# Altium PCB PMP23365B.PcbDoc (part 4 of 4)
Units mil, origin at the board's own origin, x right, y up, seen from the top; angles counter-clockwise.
Board outline 5450 x 2600 mil, 4 copper layers (Top Layer, Signal Layer 1, Signal Layer 2, Bottom Layer), stack 61.2 mil thick; 303 components, 149 nets, 783 pads, 285 vias.
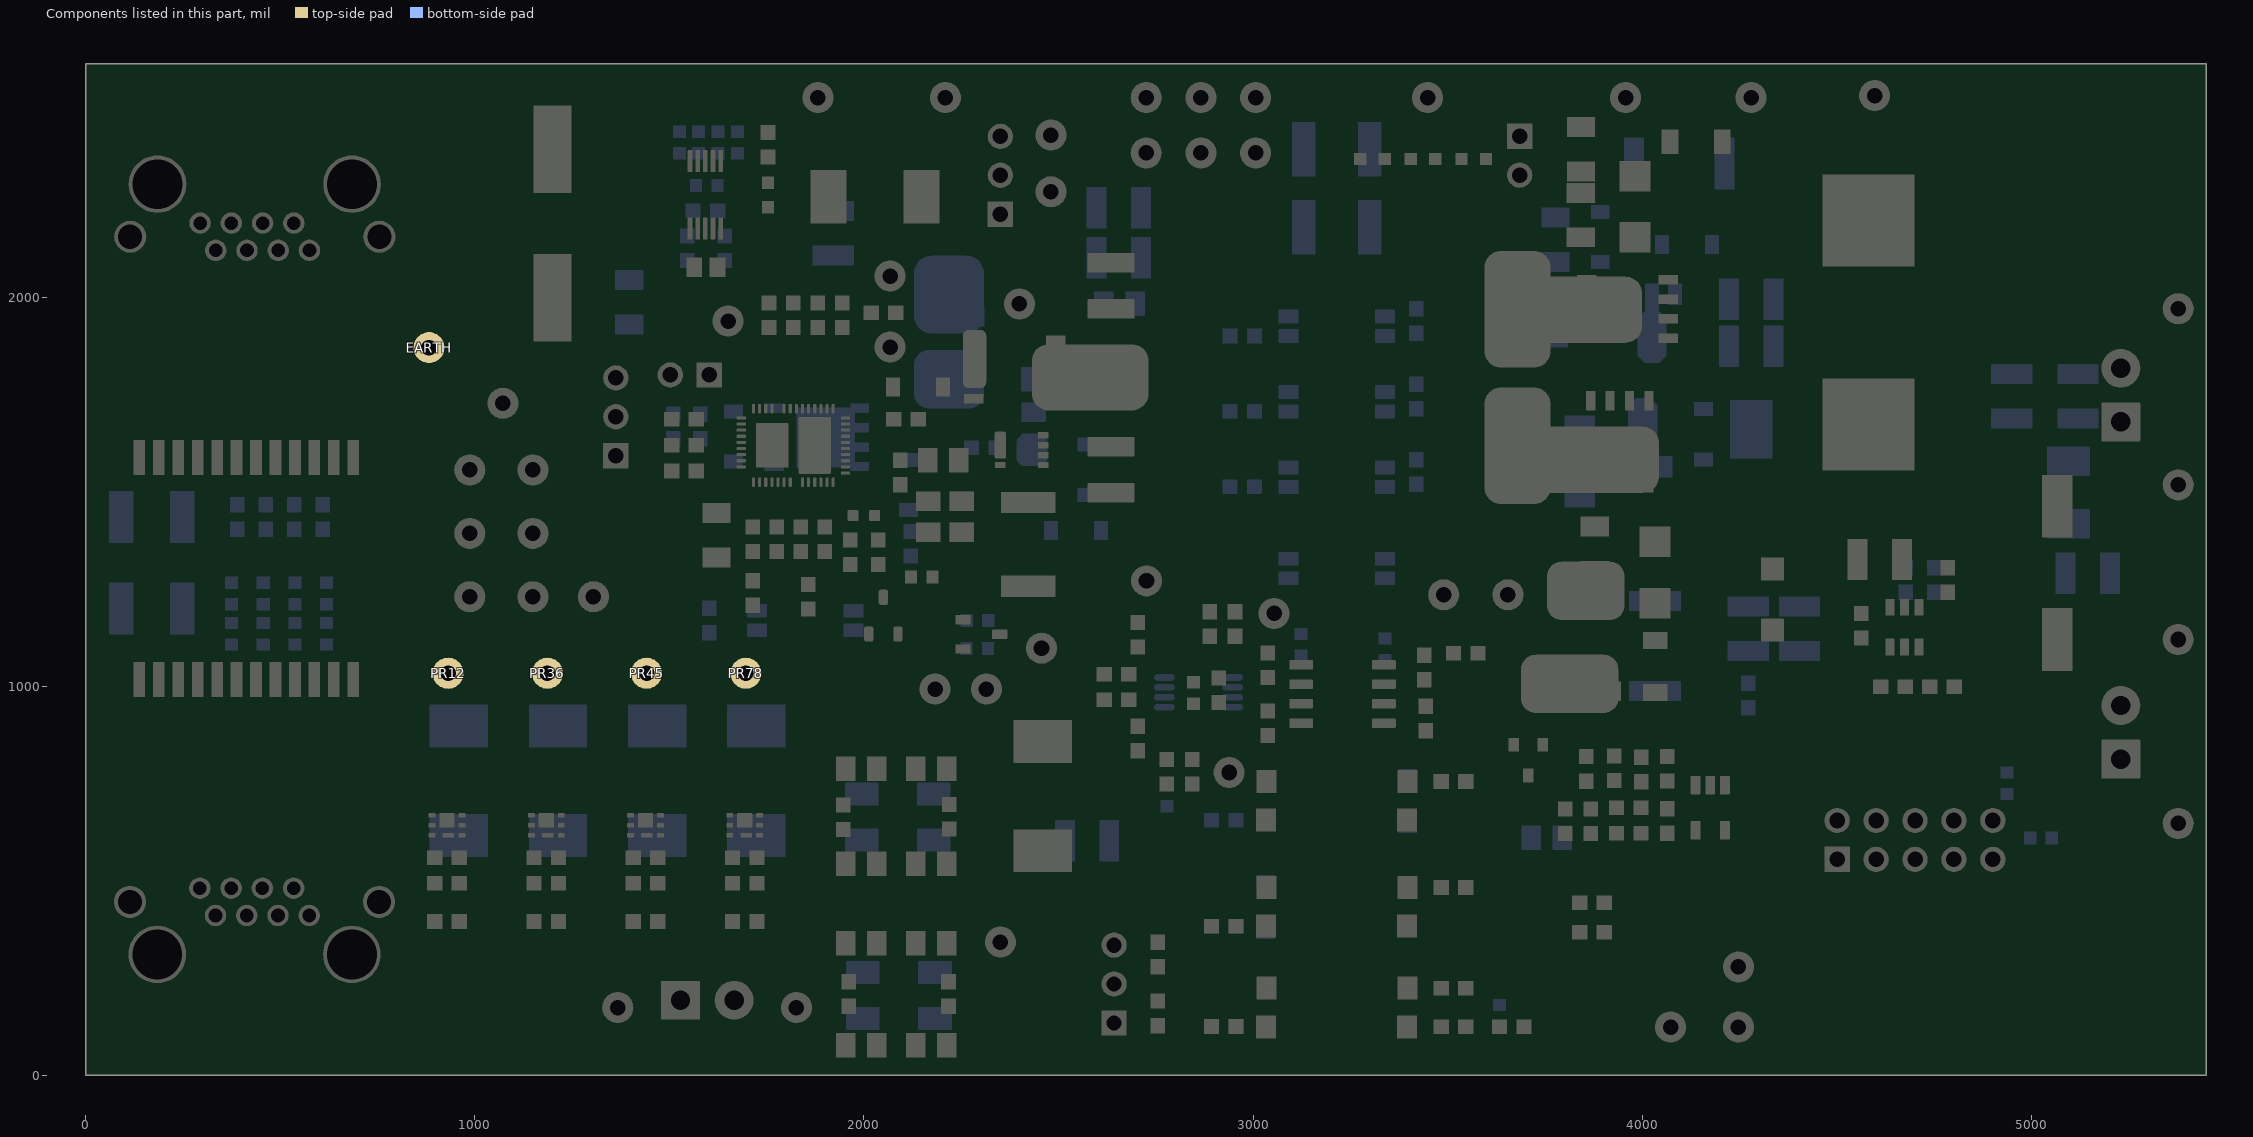
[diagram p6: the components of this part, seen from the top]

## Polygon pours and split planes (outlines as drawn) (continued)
NetC19_2 on Top Layer "TOP_LAYER_NETC19_2_P014" (solid, pour order 14): 3785.14,1540.97 cw(c3632.79,1409.24) 3833.66,1394.63 cw(c3823.69,1384.64) 3837.81,1384.62 3839.54,1382.89 ccw(c3842.66,1386.01) 3842.66,1381.6 3916.67,1381.6 cw(c3916.68,1314.41) 3964.2,1361.91 3987.72,1338.39 cw(c3984.07,1334.73) 3989.24,1334.72 ccw(c3997.54,1334.72) 3991.67,1328.85 3992.07,1328.45 ccw(c3998.48,1334.86) 3998.48,1325.79 4064.36,1325.79 ccw(c4064.36,1351.84) 4082.78,1333.42 ccw(c4071.04,1345.16) 4087.64,1345.17 4087.64,1499.56 cw(c4187.64,1499.56) 4116.93,1570.27 3901.74,1615.21
NetC19_2 on Top Layer "TOP_LAYER_NETC19_2_P011" (solid, pour order 11): 3733.67,1766.1 cw(c3733.67,1748.95) 3745.79,1761.08 3801.53,1705.33 ccw(c3872.24,1776.04) 3872.24,1676.04 4042.01,1676.04 cw(c4042.01,1663.92) 4050.58,1672.49 cw(c4036.08,1658) 4056.58,1658 4056.58,1550.67 cw(c3980.82,1550.67) 4034.39,1497.1 cw(c4020.56,1510.93) 4020.56,1491.37 3811.38,1491.37 ccw(c3811.38,1413.48) 3756.3,1468.56 cw(c3742.47,1482.39) 3742.47,1462.83 3630,1462.83 cw(c3630,1475.14) 3621.3,1466.44 3601.38,1486.35 cw(c3627.25,1512.22) 3590.67,1512.22 3590.67,1732.22 cw(c3617.55,1732.22) 3598.54,1751.23 cw(c3634.43,1715.35) 3634.43,1766.1
NetC31_1 on Top Layer "TOP_LAYER_NETC31_1_P009" (solid, pour order 9): 2339.58,1914.13 cw(c2345.74,1907.98) 2345.74,1916.68 2492.54,1916.68 cw(c2492.54,1878.68) 2519.41,1905.55 2531.01,1893.95 ccw(c2562.44,1925.38) 2562.44,1880.93 2689.57,1880.93 cw(c2689.57,1838.05) 2719.89,1868.37 cw(c2691.75,1840.23) 2731.54,1840.23 2731.54,1752.08 cw(c2678.31,1752.08) 2715.95,1714.44 cw(c2697.86,1732.53) 2697.86,1706.94 2350.16,1706.94 cw(c2350.16,1716.25) 2343.57,1709.67 2339.9,1713.34
NetC18_2 on Top Layer "TOP_LAYER_NETC18_2_P008" (solid, pour order 8): 2369.21,2113.07 2532.32,2113.07 ccw(c2532.32,2155.28) 2562.17,2125.43 cw(c2585.26,2102.34) 2585.26,2135 2666.53,2135 cw(c2666.53,2084.94) 2701.93,2120.34 2708.65,2113.63 cw(c2645.02,2050) 2735,2050 2735,1969.68 cw(c2721.29,1969.68) 2730.98,1959.99 2715.76,1944.77 cw(c2700.23,1960.3) 2700.23,1938.33 2597.39,1938.33 cw(c2597.39,1988.15) 2562.17,1952.92 2479.97,2035.12 ccw(c2409.26,1964.41) 2409.26,2064.41 2390.08,2064.41 2390.08,2075.64 ccw(c2364.2,2075.64) 2382.5,2093.94
NetC10_2 on Top Layer "TOP_LAYER_NETC10_2_P007" (solid, pour order 7): 1741.89,623.79 cw(c1741.89,616.2) 1747.25,621.57 1750.59,618.23 cw(c1739.95,607.59) 1755,607.59 1755,477.41 cw(c1750.3,477.41) 1753.62,474.09 1746.31,466.77 1719.49,466.77 cw(c1719.49,480.4) 1709.85,470.76 1704.29,476.33 1704.29,476.61 1703.31,477.59 cw(c1709.14,483.42) 1700.9,483.42 1700.9,578.34 ccw(c1684.33,578.34) 1696.04,590.06 1682.17,603.93 cw(c1687.01,608.77) 1680.16,608.77 1680.16,619.56 cw(c1684.16,619.56) 1681.33,622.38 cw(c1684.75,618.96) 1684.75,623.8 1741.6,623.8
NetC10_2 on Top Layer "TOP_LAYER_NETC10_2_P006" (solid, pour order 6): 1486.89,623.79 cw(c1486.89,616.2) 1492.25,621.57 1495.59,618.23 cw(c1484.95,607.59) 1500,607.59 1500,477.41 cw(c1495.3,477.41) 1498.62,474.09 1491.31,466.77 1464.49,466.77 cw(c1464.49,480.4) 1454.85,470.76 1449.29,476.33 1449.29,476.61 1448.31,477.59 cw(c1454.14,483.42) 1445.9,483.42 1445.9,578.34 ccw(c1429.33,578.34) 1441.04,590.06 1427.17,603.93 cw(c1432.01,608.77) 1425.16,608.77 1425.16,619.56 cw(c1429.16,619.56) 1426.33,622.38 cw(c1429.75,618.96) 1429.75,623.8 1486.6,623.8
NetC10_2 on Top Layer "TOP_LAYER_NETC10_2_P005" (solid, pour order 5): 1228.93,623.79 cw(c1228.93,616.2) 1234.3,621.57 1237.64,618.23 cw(c1227,607.59) 1242.05,607.59 1242.05,477.41 cw(c1237.35,477.41) 1240.67,474.09 1233.35,466.77 1206.54,466.77 cw(c1206.54,480.4) 1196.9,470.76 1191.34,476.33 1191.34,476.61 1190.36,477.59 cw(c1196.19,483.42) 1187.94,483.42 1187.94,578.34 ccw(c1171.38,578.34) 1183.09,590.06 1169.22,603.93 cw(c1174.06,608.77) 1167.21,608.77 1167.21,619.56 cw(c1171.2,619.56) 1168.38,622.38 cw(c1171.8,618.96) 1171.8,623.8 1228.65,623.8
NetC10_2 on Top Layer "TOP_LAYER_NETC10_2_P004" (solid, pour order 4): 976.89,623.79 cw(c976.89,616.2) 982.25,621.57 985.59,618.23 cw(c974.95,607.59) 990,607.59 990,477.41 cw(c985.3,477.41) 988.62,474.09 981.31,466.77 954.49,466.77 cw(c954.49,480.4) 944.86,470.76 939.29,476.33 939.29,476.61 938.31,477.59 cw(c944.14,483.42) 935.9,483.42 935.9,578.34 ccw(c919.33,578.34) 931.05,590.06 917.17,603.93 cw(c922.01,608.77) 915.16,608.77 915.16,619.56 cw(c919.16,619.56) 916.33,622.38 cw(c919.75,618.96) 919.75,623.8 976.6,623.8
PR78 on Top Layer "TOP_LAYER_PR78_P003" (solid, pour order 3): 1635.44,642.58 1635.44,747.48 cw(c1677.13,747.48) 1647.65,776.96 cw(c1679.22,745.39) 1679.22,790.03 1725.92,790.03 cw(c1725.92,745.39) 1757.49,776.96 cw(c1732.95,752.42) 1767.65,752.42 1767.65,668.5 cw(c1734.15,668.5) 1757.84,644.8 1752.07,639.04 cw(c1739.27,651.84) 1739.27,633.73 1645.53,633.73 cw(c1645.53,638.17) 1642.4,635.03 1635.86,641.57 cw(c1636.86,642.58) 1635.44,642.58
PR45 on Top Layer "TOP_LAYER_PR45_P002" (solid, pour order 2): 1379.56,642.58 1379.56,747.48 cw(c1421.25,747.48) 1391.77,776.96 cw(c1423.34,745.39) 1423.34,790.03 1470.04,790.03 cw(c1470.04,745.39) 1501.61,776.96 cw(c1477.07,752.42) 1511.77,752.42 1511.77,668.5 cw(c1478.26,668.5) 1501.96,644.8 1496.19,639.04 cw(c1483.38,651.84) 1483.38,633.73 1389.65,633.73 cw(c1389.65,638.17) 1386.52,635.03 1379.97,641.57 cw(c1380.97,642.58) 1379.56,642.58
PR36 on Top Layer "TOP_LAYER_PR36_P001" (solid, pour order 1): 1123.67,642.58 1123.67,747.48 cw(c1165.36,747.48) 1135.88,776.96 cw(c1167.45,745.39) 1167.45,790.03 1214.15,790.03 cw(c1214.15,745.39) 1245.72,776.96 cw(c1221.18,752.42) 1255.88,752.42 1255.88,668.5 cw(c1222.38,668.5) 1246.07,644.8 1240.3,639.04 cw(c1227.5,651.84) 1227.5,633.73 1133.77,633.73 cw(c1133.77,638.17) 1130.63,635.03 1124.09,641.57 cw(c1125.09,642.58) 1123.67,642.58
PR12 on Top Layer "TOP_LAYER_PR12_P000" (solid, pour order 0): 867.79,642.58 867.79,747.48 cw(c909.48,747.48) 880,776.96 cw(c911.57,745.39) 911.57,790.03 958.27,790.03 cw(c958.27,745.39) 989.84,776.96 cw(c965.3,752.42) 1000,752.42 1000,668.5 cw(c966.5,668.5) 990.19,644.8 984.42,639.04 cw(c971.61,651.84) 971.61,633.73 877.88,633.73 cw(c877.88,638.17) 874.75,635.03 868.2,641.57 cw(c869.21,642.58) 867.79,642.58
PGND on Bottom Layer "BOTTOM_LAYER_PGND_P038" (solid, pour order 38): 1230.78,2575 ccw(c1230.78,2506.72) 1182.5,2555 1132.41,2504.91 ccw(c1159.33,2477.99) 1121.26,2477.99 1121.26,1962.21 ccw(c1217.21,1962.21) 1149.36,1894.36 1245.61,1798.12 ccw(c1316.32,1868.83) 1316.32,1768.83 1762.11,1768.83 cw(c1762.11,1691.97) 1816.45,1746.32 cw(c1791.96,1721.82) 1826.6,1721.82 1826.6,1511.03 cw(c1763.73,1511.03) 1808.19,1466.58 1722.1,1380.49 cw(c1714.88,1387.71) 1714.88,1377.5 1704.37,1366.99 ccw(c1724.15,1347.21) 1696.18,1347.21 1696.18,1345.67 ccw(c1760.25,1345.67) 1714.94,1300.37 2256.95,758.36 cw(c2186.24,687.65) 2286.24,687.65 2286.24,152.68 ccw(c2386.24,152.68) 2315.53,81.97 2340.71,56.79 ccw(c2411.42,127.5) 2411.42,27.5 3086.62,27.5 ccw(c3086.62,82.31) 3125.37,43.55 3130.8,48.98 ccw(c3102.79,76.99) 3142.4,76.99 ccw(c3093.88,125.52) 3162.5,125.52 3162.5,2435.94 ccw(c3062.5,2435.94) 3133.21,2506.65 3094.15,2545.71 ccw(c3023.44,2475) 3023.44,2575 1479.47,2575
GND on Bottom Layer "BOTTOM_LAYER_GND_P035" (solid, pour order 35): 3413.41,2575 ccw(c3413.41,2475) 3342.7,2545.71 3298.29,2501.3 ccw(c3369,2430.59) 3269,2430.59 3269,1563.6 ccw(c3369,1563.6) 3298.29,1492.89 cw(c3268.46,1463.06) 3310.64,1463.06 3310.64,890.24 ccw(c3410.64,890.24) 3339.93,819.53 3352.8,806.67 cw(c3320.74,774.61) 3366.07,774.61 3366.07,89.13 ccw(c3405.09,89.13) 3377.5,61.54 3383.74,55.3 ccw(c3454.45,126.01) 3454.45,26.01 5306.08,26.01 ccw(c5306.08,126.01) 5376.79,55.3 5397.43,75.94 ccw(c5330.88,142.5) 5425,142.5 5425,2484.06 ccw(c5377.29,2484.06) 5411.03,2517.79 5383.11,2545.71 ccw(c5312.4,2475) 5312.4,2575 3792.19,2575
EARTH on Bottom Layer "BOTTOM_LAYER_EARTH_P017" (solid, pour order 17): 67.5,2507.5 cw(c91.64,2483.36) 91.64,2517.5 733.51,2517.5 cw(c733.51,2431.3) 794.46,2492.25 cw(c751.25,2449.05) 812.35,2449.05 812.35,153.36 cw(c761.64,153.36) 797.5,117.5 795.48,115.48 cw(c740,170.96) 740,92.5 139.32,92.5 cw(c139.32,169.32) 85,115 74.14,125.86 cw(c108.28,160) 60,160 60,2489.39 cw(c85.61,2489.39)
VSS on Bottom Layer "BOTTOM_LAYER_VSS_P020" (solid, pour order 20): 1459.27,1682.05 1459.27,1708.33 cw(c1476.79,1708.33) 1464.4,1720.72 1464.85,1721.17 cw(c1481.83,1704.18) 1481.83,1728.2 1761.35,1728.2 cw(c1761.35,1723.63) 1764.59,1726.86 cw(c1748.49,1710.77) 1771.26,1710.77 1771.26,1702.6 ccw(c1789.59,1702.6) 1776.63,1689.63 ccw(c1790.94,1703.95) 1790.94,1683.7 1801.79,1683.7 cw(c1801.79,1681.44) 1803.39,1683.04 cw(c1790.05,1669.71) 1808.91,1669.71 1808.91,1535.6 cw(c1761.09,1535.6) 1794.9,1501.79 1760.93,1467.81 cw(c1690.22,1538.52) 1690.22,1438.52 1686.33,1438.52 1678.03,1430.22 ccw(c1681.19,1427.06) 1676.72,1427.06 1676.72,1289.53 cw(c1652.86,1289.53) 1669.73,1272.65 cw(c1643.88,1298.5) 1643.88,1261.94 1627.06,1261.94 cw(c1627.06,1331.31) 1578.01,1282.26 1575.01,1285.26 cw(c1601.37,1311.62) 1564.09,1311.62 1564.09,1387.04 ccw(c1464.09,1387.04) 1534.8,1457.75 1488.56,1503.99 cw(c1559.27,1574.7) 1459.27,1574.7 1459.27,1682.24
PGND on Signal Layer 1 "SIGNAL_LAYER_1_PGND_P037" (solid, pour order 37): 1230.78,2575 ccw(c1230.78,2506.72) 1182.5,2555 1132.41,2504.91 ccw(c1159.33,2477.99) 1121.26,2477.99 1121.26,1962.21 ccw(c1217.21,1962.21) 1149.36,1894.36 1245.61,1798.12 ccw(c1316.32,1868.83) 1316.32,1768.83 1762.11,1768.83 cw(c1762.11,1691.97) 1816.45,1746.32 cw(c1791.96,1721.82) 1826.6,1721.82 1826.6,1511.03 cw(c1763.73,1511.03) 1808.19,1466.58 1722.1,1380.49 cw(c1714.88,1387.71) 1714.88,1377.5 1704.37,1366.99 ccw(c1724.15,1347.21) 1696.18,1347.21 1696.18,1345.67 ccw(c1760.25,1345.67) 1714.94,1300.37 2256.95,758.36 cw(c2186.24,687.65) 2286.24,687.65 2286.24,152.68 ccw(c2386.24,152.68) 2315.53,81.97 2340.71,56.79 ccw(c2411.42,127.5) 2411.42,27.5 3086.62,27.5 ccw(c3086.62,82.31) 3125.37,43.55 3130.8,48.98 ccw(c3102.79,76.99) 3142.4,76.99 ccw(c3093.88,125.52) 3162.5,125.52 3162.5,2435.94 ccw(c3062.5,2435.94) 3133.21,2506.65 3094.15,2545.71 ccw(c3023.44,2475) 3023.44,2575 1479.47,2575
GND on Signal Layer 1 "SIGNAL_LAYER_1_GND_P034" (solid, pour order 34): 3413.41,2575 ccw(c3413.41,2475) 3342.7,2545.71 3298.29,2501.3 ccw(c3369,2430.59) 3269,2430.59 3269,1563.6 ccw(c3369,1563.6) 3298.29,1492.89 cw(c3268.46,1463.06) 3310.64,1463.06 3310.64,890.24 ccw(c3410.64,890.24) 3339.93,819.53 3352.8,806.67 cw(c3320.74,774.61) 3366.07,774.61 3366.07,89.13 ccw(c3405.09,89.13) 3377.5,61.54 3383.74,55.3 ccw(c3454.45,126.01) 3454.45,26.01 5306.08,26.01 ccw(c5306.08,126.01) 5376.79,55.3 5397.43,75.94 ccw(c5330.88,142.5) 5425,142.5 5425,2484.06 ccw(c5377.29,2484.06) 5411.03,2517.79 5383.11,2545.71 ccw(c5312.4,2475) 5312.4,2575 3792.19,2575
EARTH on Signal Layer 1 "SIGNAL_LAYER_1_EARTH_P015" (solid, pour order 15): 67.5,2507.5 cw(c91.64,2483.36) 91.64,2517.5 733.51,2517.5 cw(c733.51,2431.3) 794.46,2492.25 cw(c751.25,2449.05) 812.35,2449.05 812.35,153.36 cw(c761.64,153.36) 797.5,117.5 795.48,115.48 cw(c740,170.96) 740,92.5 139.32,92.5 cw(c139.32,169.32) 85,115 74.14,125.86 cw(c108.28,160) 60,160 60,2489.39 cw(c85.61,2489.39)
VSS on Signal Layer 1 "SIGNAL_LAYER_1_VSS_P021" (solid, pour order 21): 1459.27,1682.05 1459.27,1708.33 cw(c1476.79,1708.33) 1464.4,1720.72 1464.85,1721.17 cw(c1481.83,1704.18) 1481.83,1728.2 1761.35,1728.2 cw(c1761.35,1723.63) 1764.59,1726.86 cw(c1748.49,1710.77) 1771.26,1710.77 1771.26,1702.6 ccw(c1789.59,1702.6) 1776.63,1689.63 ccw(c1790.94,1703.95) 1790.94,1683.7 1801.79,1683.7 cw(c1801.79,1681.44) 1803.39,1683.04 cw(c1790.05,1669.71) 1808.91,1669.71 1808.91,1535.6 cw(c1761.09,1535.6) 1794.9,1501.79 1760.93,1467.81 cw(c1690.22,1538.52) 1690.22,1438.52 1686.33,1438.52 1678.03,1430.22 ccw(c1681.19,1427.06) 1676.72,1427.06 1676.72,1289.53 cw(c1652.86,1289.53) 1669.73,1272.65 cw(c1643.88,1298.5) 1643.88,1261.94 1627.06,1261.94 cw(c1627.06,1331.31) 1578.01,1282.26 1575.01,1285.26 cw(c1601.37,1311.62) 1564.09,1311.62 1564.09,1387.04 ccw(c1464.09,1387.04) 1534.8,1457.75 1488.56,1503.99 cw(c1559.27,1574.7) 1459.27,1574.7 1459.27,1682.24
PGND on Signal Layer 2 "SIGNAL_LAYER_2_PGND_P024" (solid, pour order 24): 1230.78,2575 ccw(c1230.78,2506.72) 1182.5,2555 1132.41,2504.91 ccw(c1159.33,2477.99) 1121.26,2477.99 1121.26,1962.21 ccw(c1217.21,1962.21) 1149.36,1894.36 1245.61,1798.12 ccw(c1316.32,1868.83) 1316.32,1768.83 1762.11,1768.83 cw(c1762.11,1691.97) 1816.45,1746.32 cw(c1791.96,1721.82) 1826.6,1721.82 1826.6,1511.03 cw(c1763.73,1511.03) 1808.19,1466.58 1722.1,1380.49 cw(c1714.88,1387.71) 1714.88,1377.5 1704.37,1366.99 ccw(c1724.15,1347.21) 1696.18,1347.21 1696.18,1345.67 ccw(c1760.25,1345.67) 1714.94,1300.37 2256.95,758.36 cw(c2186.24,687.65) 2286.24,687.65 2286.24,152.68 ccw(c2386.24,152.68) 2315.53,81.97 2340.71,56.79 ccw(c2411.42,127.5) 2411.42,27.5 3086.62,27.5 ccw(c3086.62,82.31) 3125.37,43.55 3130.8,48.98 ccw(c3102.79,76.99) 3142.4,76.99 ccw(c3093.88,125.52) 3162.5,125.52 3162.5,2435.94 ccw(c3062.5,2435.94) 3133.21,2506.65 3094.15,2545.71 ccw(c3023.44,2475) 3023.44,2575 1479.47,2575
GND on Signal Layer 2 "SIGNAL_LAYER_2_GND_P036" (solid, pour order 36): 3413.41,2575 ccw(c3413.41,2475) 3342.7,2545.71 3298.29,2501.3 ccw(c3369,2430.59) 3269,2430.59 3269,1563.6 ccw(c3369,1563.6) 3298.29,1492.89 cw(c3268.46,1463.06) 3310.64,1463.06 3310.64,890.24 ccw(c3410.64,890.24) 3339.93,819.53 3352.8,806.67 cw(c3320.74,774.61) 3366.07,774.61 3366.07,89.13 ccw(c3405.09,89.13) 3377.5,61.54 3383.74,55.3 ccw(c3454.45,126.01) 3454.45,26.01 5306.08,26.01 ccw(c5306.08,126.01) 5376.79,55.3 5397.43,75.94 ccw(c5330.88,142.5) 5425,142.5 5425,2484.06 ccw(c5377.29,2484.06) 5411.03,2517.79 5383.11,2545.71 ccw(c5312.4,2475) 5312.4,2575 3792.19,2575
EARTH on Signal Layer 2 "SIGNAL_LAYER_2_EARTH_P016" (solid, pour order 16): 67.5,2507.5 cw(c91.64,2483.36) 91.64,2517.5 733.51,2517.5 cw(c733.51,2431.3) 794.46,2492.25 cw(c751.25,2449.05) 812.35,2449.05 812.35,153.36 cw(c761.64,153.36) 797.5,117.5 795.48,115.48 cw(c740,170.96) 740,92.5 139.32,92.5 cw(c139.32,169.32) 85,115 74.14,125.86 cw(c108.28,160) 60,160 60,2489.39 cw(c85.61,2489.39)
VSS on Signal Layer 2 "SIGNAL_LAYER_2_VSS_P018" (solid, pour order 18): 1459.27,1682.05 1459.27,1708.33 cw(c1476.79,1708.33) 1464.4,1720.72 1464.85,1721.17 cw(c1481.83,1704.18) 1481.83,1728.2 1761.35,1728.2 cw(c1761.35,1723.63) 1764.59,1726.86 cw(c1748.49,1710.77) 1771.26,1710.77 1771.26,1702.6 ccw(c1789.59,1702.6) 1776.63,1689.63 ccw(c1790.94,1703.95) 1790.94,1683.7 1801.79,1683.7 cw(c1801.79,1681.44) 1803.39,1683.04 cw(c1790.05,1669.71) 1808.91,1669.71 1808.91,1535.6 cw(c1761.09,1535.6) 1794.9,1501.79 1760.93,1467.81 cw(c1690.22,1538.52) 1690.22,1438.52 1686.33,1438.52 1678.03,1430.22 ccw(c1681.19,1427.06) 1676.72,1427.06 1676.72,1289.53 cw(c1652.86,1289.53) 1669.73,1272.65 cw(c1643.88,1298.5) 1643.88,1261.94 1627.06,1261.94 cw(c1627.06,1331.31) 1578.01,1282.26 1575.01,1285.26 cw(c1601.37,1311.62) 1564.09,1311.62 1564.09,1387.04 ccw(c1464.09,1387.04) 1534.8,1457.75 1488.56,1503.99 cw(c1559.27,1574.7) 1459.27,1574.7 1459.27,1682.24

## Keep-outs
Keep-Out Layer:
  text ".Layer_Name" at 596.68,-878.18 h40

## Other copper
Top Layer:
  pour cut-out: 3317.25,2229.12 2859.29,2229.12 ccw(c2859.29,2192.95) 2833.71,2218.52 2822.51,2218.52 ccw(c2822.51,2182.87) 2797.3,2208.08 2756.6,2167.38 ccw(c2827.31,2096.67) 2727.31,2096.67 2727.31,1527.68 ccw(c2827.31,1527.68) 2756.6,1456.97 2821.31,1392.26 ccw(c2892.02,1462.97) 2892.02,1362.97 3334.75,1362.97 3334.75,2230.09
  pour cut-out: 3212.39,2218.55 3713.84,2218.55 cw(c3713.84,2181.76) 3739.85,2207.77 3742.41,2205.2 cw(c3705.99,2168.78) 3757.5,2168.78 3757.5,1501.22 cw(c3657.5,1501.22) 3728.21,1430.51 3679.26,1381.56 cw(c3608.55,1452.27) 3608.55,1352.27 3214.89,1352.27 3214.89,1352.39
  text ".Layer_Name" at 596.68,-878.18 h40
Bottom Layer:
  text ".Layer_Name" at 596.68,-878.18 h40

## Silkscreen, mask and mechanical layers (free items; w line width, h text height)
Top Overlay:
  text "PMP23365 / Rev. B" at 5044.37,2427.87 h80
  text ".Layer_Name" at 596.68,-878.18 h40
Bottom Overlay:
  text ".Layer_Name" at 596.68,-878.18 h40
Top Paste:
  text ".Layer_Name" at 596.68,-878.18 h40
Bottom Paste:
  text ".Layer_Name" at 596.68,-878.18 h40
Top Solder:
  text ".Layer_Name" at 596.68,-878.18 h40
  text ".Layer_Name" at 596.68,-878.18 h40
Bottom Solder:
  text ".Layer_Name" at 596.68,-878.18 h40
Drill Guide:
  text ".Layer_Name" at 596.68,-878.18 h40
M1 Board Outline:
  lines w10: 5450,0 0,0 0,2600 5450,2600 5450,3.36
  text ".Layer_Name" at 596.68,-878.18 h40
M2 Board Dimensions:
  rectangle: 19.68,-294.68 144.68,-169.68
  rectangle: 144.68,-419.68 519.68,-294.68
  lines w7: 19.68,-294.68 1019.68,-294.68 ; 144.68,-419.68 144.68,-169.68 ; 269.68,-419.68 269.68,-169.68 ; 519.68,-419.68 519.68,-169.68 ; 769.68,-419.68 769.68,-169.68 ; 19.68,-419.68 1019.68,-419.68 1019.68,-169.68 19.68,-169.68 19.68,-419.68
  text ".Layer_Name" at 596.68,-878.18 h40
M3 3D STEP Top:
  text ".Layer_Name" at 596.68,-878.18 h40
M4 3D STEP Bottom:
  text ".Layer_Name" at 596.68,-878.18 h40
M5 Assembly Top:
  lines w10: -272.32,-949.85 6327.68,-949.85 ; -272.32,-746.52 6329.68,-746.52 ; -272.32,-543.18 -272.32,-1153.18 3732.68,-1153.18 6329.68,-1153.18 6329.68,-543.19 -271.82,-543.19 -271.82,-1153.18 1303.68,-1153.18 ; 2192.68,-1153.18 2192.68,-543.19 ; 3459.68,-746.52 3459.68,-543.19 ; 4299.68,-746.52 4299.68,-543.19 ; 4921.68,-1159.68 4921.68,-956.85
  text "COMPONENTS MARKED 'DNP' SHOULD NOT BE POPULATED." at 1173.18,-338.18 h40
  text "ASSEMBLY VARIANT:" at 1172.68,-453.68 h40
  text ".VariantName" at 2208.68,-453.68 h40
  text "PCB VIEWED FROM TOP SIDE" at -208.82,-675.35 h40
  text "BOARD #:" at 2267.68,-675.35 h40
  text ".PRJ_Number" at 2813.18,-675.35 h40
  text "REV:" at 3657.68,-675.35 h40
  text ".PCB_Rev" at 3949.18,-675.35 h40
  text "SVN REV:" at 4495.68,-675.35 h40
  text ".VersionControl_RevNumber" at 5001.68,-675.35 h40
  text "TID #:" at 2267.68,-878.69 h40
  text ".TID" at 2813.18,-878.69 h40
  text "PLOT NAME =" at -208.82,-1084.02 h40
  text ".plot_File_Name" at 596.68,-1084.02 h40
  text "GENERATED    :" at 2269.68,-1084.02 h40
  text ".Print_Date" at 3139.18,-1084.02 h40
  text ".Print_Time" at 3868.18,-1084.02 h40
  text "TEXAS INSTRUMENTS" at 5132.68,-1084.02 h40
M6 Assembly Bottom:
  lines w10: -272.82,-747.02 6329.18,-747.02 ; -270.82,-950.35 6329.18,-950.35 ; 1135.18,-1160.18 1135.18,-957.35 ; 1757.18,-747.02 1757.18,-543.69 ; 2597.18,-747.02 2597.18,-543.69 ; 3864.18,-1153.68 3864.18,-543.69 ; 4753.18,-1153.68 6328.68,-1153.68 6328.68,-543.68 -272.82,-543.69 -272.82,-1153.68 2324.18,-1153.68 6329.18,-1153.68 6329.18,-543.68
  text "COMPONENTS MARKED 'DNP' SHOULD NOT BE POPULATED." at 6121.68,-337.68 h40
  text ".VariantName" at 5077.68,-453.68 h40
  text "ASSEMBLY VARIANT:" at 6116.68,-453.68 h40
  text ".VersionControl_RevNumber" at 1055.18,-675.85 h40
  text "SVN REV:" at 1561.18,-675.85 h40
  text ".PCB_Rev" at 2107.68,-675.85 h40
  text "REV:" at 2399.18,-675.85 h40
  text ".PRJ_Number" at 3243.68,-675.85 h40
  text "BOARD #:" at 3789.18,-675.85 h40
  text "PCB VIEWED FROM BOTTOM SIDE" at 6265.68,-675.85 h40
  text ".TID" at 3243.68,-879.19 h40
  text "TID #:" at 3789.18,-879.19 h40
  text "TEXAS INSTRUMENTS" at 924.18,-1084.52 h40
  text ".Print_Time" at 2188.68,-1084.52 h40
  text ".Print_Date" at 2917.68,-1084.52 h40
  text "GENERATED    :" at 3787.18,-1084.52 h40
  text ".plot_File_Name" at 5460.18,-1084.52 h40
  text "PLOT NAME =" at 6265.68,-1084.52 h40
M9 Title Sheet:
  drawing of 57 lines, arcs and shapes, not listed
  text "1" at 759.52,8016.82 h70
  text "2" at 3255.18,8016.82 h70
  text "3" at 5744.53,8016.82 h70
  text "4" at 8251.2,8016.82 h70
  text "5" at 10750.18,8016.82 h70
  text "6" at 13255.18,8016.82 h70
  text "A" at -396.82,6873.82 h70
  text "A" at 14403.18,6873.82 h70
  text "B" at -396.82,4493.82 h70
  text "B" at 14403.18,4493.82 h70
  text "C" at -396.82,2118.82 h70
  text "C" at 14403.18,2118.82 h70
  text "PROJECT TITLE:" at 11363.18,257.82 h45
  text ".PRJ_Title" at 11413.18,124.49 h70
  text "DESIGNED FOR:" at 11363.18,-43.18 h45
  text ".PRJ_Customer" at 11413.18,-183.18 h70
  text "D" at -396.82,-251.18 h70
  text "D" at 14403.18,-251.18 h70
  text "FILE NAME:" at 11363.18,-343.18 h45
  text ".PCB_File_Name_No_Path" at 11413.18,-463.18 h70
  text "Texas Instruments (TI) and/or its licensors do not warrant the accuracy or completeness of this specification" at 6393.68,-625.02 h45
  text "ENGINEER:" at 11363.18,-633.18 h45
  text "LAYOUT BY:" at 12868.18,-633.18 h45
  text "or any information contained therein. TI and/or its licensors do not warrant that this design will meet" at 6348.7,-737.69 h45
  text ".PRJ_Engineer" at 11413.18,-788.18 h70
  text ".PCB_Layout" at 12918.68,-788.18 h70
  text "the specifications, will be suitable for your application or fit for any particular purpose, or will operate in" at 6348.7,-850.35 h45
  text ".Layer_Name" at 596.68,-878.18 h40
  text "ALTIUM DESIGNER VERSION:" at 12868.18,-943.18 h45
  text "an implementation. TI and/or its licensors do not warrant that the design is production worthy. You should" at 6348.7,-963.02 h45
  text "completely validate and test your design implementation to confirm the system functionality for your application." at 6393.68,-1075.68 h45
  text ".print_Scale" at 11413.18,-1076.51 h70
  text ".Application_BuildNumber" at 12918.68,-1076.51 h70
  text "1" at 759.52,-1283.18 h70
  text "2" at 3255.18,-1283.18 h70
  text "3" at 5744.53,-1283.18 h70
  text "4" at 8251.2,-1283.18 h70
  text "5" at 10750.18,-1283.18 h70
  text "6" at 13255.18,-1283.18 h70
M10 Fab Notes:
  drawing of 189 lines, arcs and shapes, not listed
  text "DESIGN INFORMATION" at 12401.7,6336.49 h40
  text "MIN. TRACK WIDTH:" at 11757.14,6204.36 h40
  text "8" at 12853.39,6204.37 h40
  text "MIL" at 13008.14,6204.36 h40
  text "MIN. CLEARANCE:" at 11757.14,6080.24 h40
  text "0.2" at 12793.39,6080.24 h40
  text "mm" at 13008.14,6080.24 h40
  text "MIN. VIA PAD SIZE:" at 11757.14,5956.11 h40
  text "24" at 12823.4,5956.11 h40
  text "MIL" at 13008.14,5956.11 h40
  text "0.05mm (2MIL)" at 12452.14,5826.21 h40
  text "MINIMUM ANNULAR RING" at 11427.91,5817.99 h40
  text "EXTERNAL" at 13160.14,5817.99 h40
  text "PER" at 11627.91,5707.86 h40
  text "IPC-D-275 CLASS 2 LEVEL C" at 11847.91,5707.86 h40
  text "MIL, HOLES" at 13336.14,5607.38 h40
  text "+/-" at 12943.68,5598.8 h40
  text "+/-" at 13797.68,5598.8 h40
  text "REGISTRATION TOLERANCES:" at 11427.91,5597.73 h40
  text "METAL" at 12627.68,5597.73 h40
  text "5" at 13203.89,5597.74 h40
  text "3" at 14036.89,5597.74 h40
  text "MIL" at 14153.14,5597.73 h40
  text "HOLE SIZE TOLERANCE (UNLESS OTHERWISE SPECIFIED):" at 11427.91,5499.42 h40
  text "+/-" at 13797.68,5496.55 h40
  text "3" at 14036.89,5495.48 h40
  text "MIL" at 14153.14,5495.48 h40
  text "MATERIAL:" at 11353.14,5357.83 h40
  text "FR-4 High Tg" at 12339.59,5229.31 h40
  text "X" at 12195.15,5221.32 h40
  text "FR-408" at 11774.15,5216.8 h40
  text "OTHER" at 13262.14,5216.8 h40
  text "62 MIL (1.6mm) +/-10%" at 12094.25,5073.77 h40
  text "X" at 11974.15,5071.32 h40
  text "THICKNESS:" at 11427.91,5065.55 h40
  text "OTHER" at 13379.14,5065.55 h40
  text "TOLERANCE:" at 11427.91,4927.24 h40
  text "X" at 12276.15,4927.24 h40
  text "ANSI IPC-6012 TYPE 3 CLASS 2" at 12454.16,4927.24 h40
  text "OTHER +/-" at 12454.14,4783.05 h40
  text "BOW & TWIST:" at 11427.91,4637.86 h40
  text "X" at 12276.15,4637.86 h40
  text "ANSI IPC-6012 TYPE 3 CLASS 2" at 12454.16,4637.86 h40
  text "OTHER +/-" at 12454.14,4491.16 h40
  text "DRILLING:" at 11353.14,4360.54 h40
  text "NC_DRILL FILES" at 13114.14,4255.36 h40
  text "REFERENCE:" at 11427.91,4251.42 h40
  text "X" at 12085.15,4251.32 h40
  text "AS SHOWN" at 12263.14,4251.42 h40
  text "X" at 12986.15,4251.42 h40
  text "OTHER" at 13412.14,4109.17 h40
  text "PTH COPPER THICKNESS:" at 11427.59,4105.64 h40
  text "X" at 12566.83,4105.64 h40
  text "20-30 um" at 12694.82,4105.64 h40
  text "BOARD FINISH:" at 11353.14,3958.04 h40
  text "SILKSCREEN:" at 11508.37,3847.91 h40
  text "X" at 12466.15,3847.91 h40
  text "TOP" at 12583.14,3847.91 h40
  text "X" at 12976.15,3847.91 h40
  text "BOTTOM" at 13094.14,3847.91 h40
  text "SILKSCREEN COLOR:" at 11508.37,3692.73 h40
  text "X" at 12465.15,3692.73 h40
  text "WHITE" at 12583.14,3692.73 h40
  text "OTHER" at 13094.14,3692.73 h40
  text "X" at 12596.15,3549.28 h40
  text "GREEN" at 12714.14,3549.28 h40
  text "OTHER" at 13332.14,3549.28 h40
  text "SOLDER RESIST COLOR:" at 11508.37,3542.41 h40
  text "X" at 12596.15,3395.03 h40
  text "MATTE" at 12714.14,3395.03 h40
  text "SEMI-GLOSS" at 13331.68,3394.39 h40
  text "IMMERSION GOLD (ENIG)" at 12414.14,3222.25 h40
  text "ENEPIG" at 13751.68,3215.03 h40
  text "SURFACE FINISH:" at 11353.14,3214.03 h40
  text "X" at 12236.15,3214.03 h40
  text "IMM. TIN/SILVER OR EQUIV" at 11682.68,3076.72 h40
  text "OTHER" at 13114.14,3072.78 h40
  text "ARRAY/PANEL:" at 11353.14,2917.4 h40
  text "CUT AND TRIM PER M1 BOARD OUTLINE" at 12414.15,2909.18 h40
  text "N.C. ROUTE" at 12414.14,2773.21 h40
  text "X" at 13102.15,2773.21 h40
  text "V. SCORE" at 13280.14,2773.21 h40
  text "CERTIFICATION:" at 11353.14,2644.09 h40
  text "MATERIALS AND WORKMANSHIP FOR ALL PCBS" at 12078.14,2644.09 h40
  text "TO MEET OR EXCEED THE REQUIREMENTS OF:" at 12078.14,2550.02 h40
  text "X" at 11715.65,2421.39 h40
  text "ANSI IPC-A-600F CLASS ->" at 11843.65,2421.39 h40
  text "X" at 13491.65,2421.39 h40
  text "2" at 13601.65,2421.39 h40
  text "1" at 13286.65,2419.9 h40
  text "3" at 13955.65,2419.9 h40
  text "X" at 12527.65,2273.71 h40
  text "RoHS" at 12655.65,2273.71 h40
  text "OTHER" at 13300.05,2273.71 h40
  text "PER ORDER" at 13697.11,2273.71 h40
  text "ALL BOARDS MUST MEET OR EXCEED UL94-V0 REQUIREMENTS." at 11380.68,2119.88 h40
  text "PCB MUST BEAR THE UL94V-0 UL REGISTERED MATERIAL ID NUMBER" at 11380.68,2003.82 h40
  text "ADDITIONAL REQUIREMENTS:" at 11353.14,1834.39 h40
  text "MICROSECTION:" at 11427.91,1727.27 h40
  text "YES" at 12333.65,1727.27 h40
  text "REQUIRED" at 13195.14,1582.94 h40
  text "BARE BOARD ELEC. TEST:" at 11427.91,1580.08 h40
  text "NONE" at 12733.65,1580.08 h40
  text "X" at 13077.15,1580.08 h40
  text "PER ORDER" at 13787.14,1580.08 h40
  text "XX MIL VIAS REQUIRE NON-CONDUCTIVE FILL AND PLANARIZE" at 11596.06,1375.13 h59
  text "XX MIL VIAS REQUIRE CONDUCTIVE FILL AND PLANARIZE" at 11604.06,1271.16 h40
  text "OUTER XX MIL TRACES REQUIRE 50 OHM SINGLE-ENDED IMPEDANCE" at 11603.08,1107.77 h58
  text "LAYER 2 & 3 (INNER LAYERS) XX MIL WIDE, XX MIL SPACE / TRACES REQUIRE 100 OHM DIFFERENTIAL IMPEDANCE" at 11595.08,872.06 h40
  text ".Layer_Name" at 596.68,-878.18 h40
M11 Gerber Information:
  lines w10: -272.32,-949.85 6327.68,-949.85 ; -272.32,-746.52 6329.68,-746.52 ; -272.32,-543.18 -272.32,-1153.18 3732.68,-1153.18 6329.68,-1153.18 6329.68,-543.19 -271.82,-543.19 -271.82,-1153.18 1303.68,-1153.18 ; 2192.68,-1153.18 2192.68,-543.19 ; 3459.68,-746.52 3459.68,-543.19 ; 4299.68,-746.52 4299.68,-543.19 ; 4921.68,-1159.68 4921.68,-956.85
  text "ALL ARTWORK VIEWED FROM TOP SIDE" at -208.82,-675.35 h40
  text "BOARD #:" at 2267.68,-675.35 h40
  text ".PRJ_Number" at 2813.18,-675.35 h40
  text "REV:" at 3657.68,-675.35 h40
  text ".PCB_Rev" at 3949.18,-675.35 h40
  text "SVN REV:" at 4495.68,-675.35 h40
  text ".VersionControl_RevNumber" at 5001.68,-675.35 h40
  text "LAYER NAME =" at -208.82,-878.18 h40
  text "TID #:" at 2267.68,-878.69 h40
  text ".TID" at 2813.18,-878.69 h40
  text "PLOT NAME =" at -208.82,-1084.02 h40
  text ".plot_File_Name" at 596.68,-1084.02 h40
  text "GENERATED    :" at 2269.68,-1084.02 h40
  text ".Print_Date" at 3139.18,-1084.02 h40
  text ".Print_Time" at 3868.18,-1084.02 h40
  text "TEXAS INSTRUMENTS" at 5132.68,-1084.02 h40
M12 Stackup:
  drawing of 295 lines, arcs and shapes, not listed
  text "Layer" at 6689,7165.35 h40
  text "Name" at 6968.95,7165.35 h40
  text "Material" at 7602.11,7165.35 h40
  text "Thickness" at 8181.95,7165.35 h40
  text "Constant" at 8621.84,7165.35 h40
  text "Board Layer Stack" at 9008.42,7165.35 h40
  text "Top Overlay" at 6968.95,7085.35 h40
  text "Top Solder" at 6968.95,7005.35 h40
  text "Solder Resist" at 7602.11,7005.35 h40
  text "0.40mil" at 8181.95,7005.35 h40
  text "3.5" at 8621.84,7005.35 h40
  text "1" at 6689,6925.35 h40
  text "Top Layer" at 6968.95,6925.35 h40
  text "2.80mil" at 8181.95,6925.35 h40
  text "Dielectric 1" at 6968.95,6845.35 h40
  text "FR-4" at 7602.11,6845.35 h40
  text "15.00mil" at 8181.95,6845.35 h40
  text "4.8" at 8621.84,6845.35 h40
  text "2" at 6689,6765.35 h40
  text "Signal Layer 1" at 6968.95,6765.35 h40
  text "2.80mil" at 8181.95,6765.35 h40
  text "Dielectric 2" at 6968.95,6685.35 h40
  text "FR-4" at 7602.11,6685.35 h40
  text "20.00mil" at 8181.95,6685.35 h40
  text "4.2" at 8621.84,6685.35 h40
  text "3" at 6689,6605.35 h40
  text "Signal Layer 2" at 6968.95,6605.35 h40
  text "2.80mil" at 8181.95,6605.35 h40
  text "Dielectric 3" at 6968.95,6525.35 h40
  text "FR-4" at 7602.11,6525.35 h40
  text "15.00mil" at 8181.95,6525.35 h40
  text "4.2" at 8621.84,6525.35 h40
  text "4" at 6689,6445.35 h40
  text "Bottom Layer" at 6968.95,6445.35 h40
  text "2.80mil" at 8181.95,6445.35 h40
  text "Bottom Solder" at 6968.95,6365.35 h40
  text "Solder Resist" at 7602.11,6365.35 h40
  text "0.40mil" at 8181.95,6365.35 h40
  text "3.5" at 8621.84,6365.35 h40
  text "Bottom Overlay" at 6968.95,6285.35 h40
  text ".Layer_Name" at 596.68,-878.18 h40
M13 Component Bodies Top:
  text ".Layer_Name" at 596.68,-878.18 h40
M14 Component Bodies Bottom:
  text ".Layer_Name" at 596.68,-878.18 h40
M15 Courtyards Top:
  text ".Layer_Name" at 596.68,-878.18 h40
M16 Courtyards Bottom:
  text ".Layer_Name" at 596.68,-878.18 h40
Drill Drawing:
  circle w10: c6407.53,2603.36 r27.23
  lines w10: 6380.3,1650.36 6434.75,1650.36 6407.53,1595.91 6380.3,1650.36 ; 6380.3,1718.43 6434.75,1718.43 6434.75,1772.89 6380.3,1772.89 6380.3,1718.43 ; 6380.3,1840.96 6434.75,1840.96 6434.75,1895.42 6380.3,1895.42 6380.3,1840.96 ; 6380.3,1977.1 6393.91,1977.1 6393.91,1963.49 6421.14,1963.49 6421.14,1977.1 6434.75,1977.1 6434.75,2004.33 6421.14,2004.33 6421.14,2017.95 6393.91,2017.95 6393.91,2004.33 6380.3,2004.33 6380.3,1977.1 ; 6380.3,2113.25 6407.53,2086.02 6434.75,2113.25 6407.53,2140.47 6380.3,2113.25 ; 6380.3,2222.16 6393.91,2222.16 6407.53,2208.55 6421.14,2222.16 6434.75,2222.16 6421.14,2235.77 6434.75,2249.39 6421.14,2249.39 6407.53,2263 6393.91,2249.39 6380.3,2249.39 6393.91,2235.77 6380.3,2222.16 ; 6380.3,2331.07 6380.3,2344.69 6393.91,2358.3 6380.3,2371.92 6380.3,2385.53 6393.91,2385.53 6407.53,2371.92 6421.14,2385.53 6434.75,2385.53 6434.75,2371.92 6421.14,2358.3 6434.75,2344.69 6434.75,2331.07 6421.14,2331.07 6407.53,2344.69 6393.91,2331.07 6380.3,2331.07 ; 6380.3,2453.6 6407.53,2467.22 6434.75,2453.6 6421.14,2480.83 6434.75,2508.06 6407.53,2494.44 6380.3,2508.06 6393.91,2480.83 6380.3,2453.6 ; 6380.3,2753.11 6434.75,2753.11 6407.53,2698.66 6380.3,2753.11 ; 6391.19,1851.85 6423.86,1851.85 6423.86,1884.53 6391.19,1884.53 6391.19,1851.85 ; 6391.19,2742.22 6423.86,2742.22 6407.53,2709.55 6391.19,2742.22
  lines w12: 6330.88,1559.15 9514.6,1559.15 ; 6330.88,2784.43 9514.6,2784.43 ; 6663.74,1436.62 6663.74,2906.96 ; 6990.8,1436.62 6990.8,2906.96 ; 7617.85,1436.62 7617.85,2906.96 ; 7873.14,1436.62 7873.14,2906.96 ; 8242.71,1436.62 8242.71,2906.96 ; 8956.6,1436.62 8956.6,2906.96 ; 6330.88,1436.62 9514.6,1436.62 9514.6,2906.96 6330.88,2906.96 6330.88,1436.62
  text "Symbol" at 6404.4,2821.19 h70.95
  text "Quantity" at 6700.5,2821.19 h70.95
  text "Finished Hole Size" at 7027.56,2821.19 h70.95
  text "Plated" at 7654.61,2821.19 h70.95
  text "Hole Type" at 7909.9,2821.19 h70.95
  text "Drill Layer Pair" at 8279.47,2821.19 h70.95
  text "Hole Tolerance" at 8993.36,2821.19 h70.95
  text "13" at 6700.5,2698.66 h59.12
  text "7.87mil (0.200mm)" at 7027.56,2698.66 h59.12
  text "PTH" at 7654.61,2698.66 h59.12
  text "Round" at 7909.9,2698.66 h59.12
  text "Top Layer - Bottom Layer" at 8279.47,2698.66 h59.12
  text "261" at 6700.5,2576.13 h59.12
  text "16.00mil (0.406mm)" at 7027.56,2576.13 h59.12
  text "PTH" at 7654.61,2576.13 h59.12
  text "Round" at 7909.9,2576.13 h59.12
  text "Top Layer - Bottom Layer" at 8279.47,2576.13 h59.12
  text "4" at 6700.5,2453.6 h59.12
  text "28.00mil (0.711mm)" at 7027.56,2453.6 h59.12
  text "PTH" at 7654.61,2453.6 h59.12
  text "Round" at 7909.9,2453.6 h59.12
  text "Top Layer - Bottom Layer" at 8279.47,2453.6 h59.12
  text "7" at 6700.5,2331.07 h59.12
  text "30.00mil (0.762mm)" at 7027.56,2331.07 h59.12
  text "PTH" at 7654.61,2331.07 h59.12
  text "Round" at 7909.9,2331.07 h59.12
  text "Top Layer - Bottom Layer" at 8279.47,2331.07 h59.12
  text "16" at 6700.5,2208.55 h59.12
  text "35.04mil (0.890mm)" at 7027.56,2208.55 h59.12
  text "PTH" at 7654.61,2208.55 h59.12
  text "Round" at 7909.9,2208.55 h59.12
  text "Top Layer - Bottom Layer" at 8279.47,2208.55 h59.12
  text "13" at 6700.5,2086.02 h59.12
  text "39.37mil (1.000mm)" at 7027.56,2086.02 h59.12
  text "PTH" at 7654.61,2086.02 h59.12
  text "Round" at 7909.9,2086.02 h59.12
  text "Top Layer - Bottom Layer" at 8279.47,2086.02 h59.12
  text "59" at 6700.5,1963.49 h59.12
  text "40.00mil (1.016mm)" at 7027.56,1963.49 h59.12
  text "PTH" at 7654.61,1963.49 h59.12
  text "Round" at 7909.9,1963.49 h59.12
  text "Top Layer - Bottom Layer" at 8279.47,1963.49 h59.12
  text "6" at 6700.5,1840.96 h59.12
  text "50.00mil (1.270mm)" at 7027.56,1840.96 h59.12
  text "PTH" at 7654.61,1840.96 h59.12
  text "Round" at 7909.9,1840.96 h59.12
  text "Top Layer - Bottom Layer" at 8279.47,1840.96 h59.12
  text "4" at 6700.5,1718.43 h59.12
  text "61.81mil (1.570mm)" at 7027.56,1718.43 h59.12
  text "PTH" at 7654.61,1718.43 h59.12
  text "Round" at 7909.9,1718.43 h59.12
  text "Top Layer - Bottom Layer" at 8279.47,1718.43 h59.12
  text "4" at 6700.5,1595.91 h59.12
  text "128.00mil (3.251mm)" at 7027.56,1595.91 h59.12
  text "PTH" at 7654.61,1595.91 h59.12
  text "Round" at 7909.9,1595.91 h59.12
  text "Top Layer - Bottom Layer" at 8279.47,1595.91 h59.12
  text "387 Total" at 6700.5,1473.38 h59.12
  text ".Layer_Name" at 596.68,-878.18 h40
Mechanical 17:
  text ".Layer_Name" at 596.68,-878.18 h40
Mechanical 18:
  text ".Layer_Name" at 596.68,-878.18 h40
Mechanical 19:
  text ".Layer_Name" at 596.68,-878.18 h40

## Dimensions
0,0 to 5450,0 on M2 Board Dimensions
0,0 to 0,2600 on M2 Board Dimensions
19.68,-419.68 to 1019.68,-419.68 on M2 Board Dimensions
